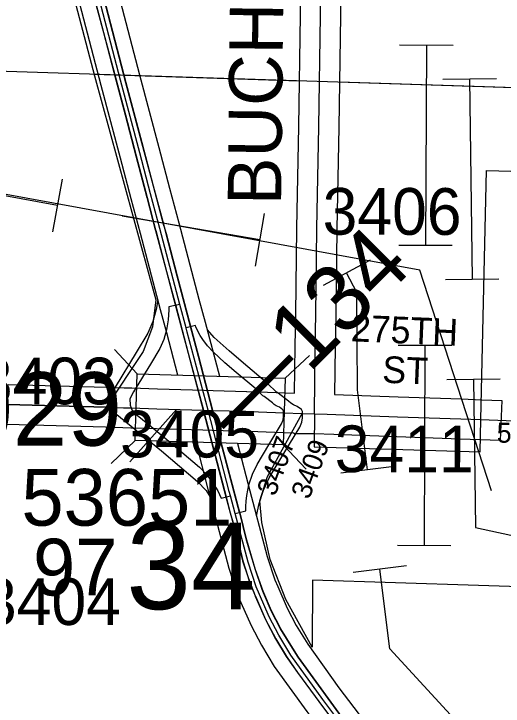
# Model space of a CAD drawing. Extents: x -157.2 to -99.3, y 12.2 to 46.2.
# Drawn here: x -143.818 to -143.085, y 23.189 to 24.227 of the extents above; entities that cross this region are included whole.
import ezdxf

# ---------------------------------------------------------------- set-up
doc = ezdxf.new("R2010")
doc.units = 0
for name, color, linetype in [('tdCoCorpBndry', 7, 'Continuous'), ('tdCoDivCarto', 7, 'Continuous'), ('tdCoInt', 7, 'Continuous'), ('tdCoIntCL', 7, 'Continuous'), ('tdCoIntRamp', 7, 'Continuous'), ('tdCoIntRte', 7, 'Continuous'), ('tdCoPipe', 7, 'Continuous'), ('tdCoPipe1', 7, 'Continuous'), ('tdCoPipe2', 7, 'Continuous'), ('tdCoSecRdNmbr', 7, 'Continuous'), ('tdCoSecRdTxt', 7, 'Continuous'), ('tdCoSecRteBand', 7, 'Continuous'), ('tdCoSecRteCL', 7, 'Continuous'), ('tdCoSectLine', 7, 'Continuous'), ('tdCoSectLinePart', 7, 'Continuous'), ('tdCoSectNmbr', 7, 'Continuous'), ('tdCoStrucNonDivPri', 7, 'Continuous'), ('tdCoStrucPriMaintName', 7, 'Continuous'), ('tdCoStrucSecCoName', 7, 'Continuous'), ('tdCoStrucSecFHWANum', 7, 'Continuous'), ('tdCoSurfConc', 7, 'Continuous'), ('tdCoSurfConcUnbanded', 7, 'Continuous'), ('tdCoSurfEarth', 7, 'Continuous'), ('tdStHwyIntRefPost1', 7, 'Continuous')]:
    doc.layers.add(name, color=color, linetype=linetype)

msp = doc.modelspace()

# ---------------------------------------------------------------- linework, layer by layer
at = {"layer": 'tdCoCorpBndry'}
for points in [[(-143.7635, 24.3875), (-143.6972, 24.1343), (-143.6054, 23.7984), (-143.6103, 23.7579), (-143.6243, 23.7211), (-143.68, 23.6375), (-143.8278, 23.6417), (-143.8666, 23.6435), (-143.8652, 23.7494), (-143.8627, 23.9001), (-143.861, 24.0683), (-143.8604, 24.1421), (-144.3519, 24.154), (-144.3395, 24.6706)], [(-142.873, 23.3623), (-143.3705, 23.3785), (-143.371, 23.2779), (-143.4103, 23.3495), (-143.4338, 23.4091), (-143.4466, 23.4647), (-143.4493, 23.4974), (-143.438, 23.5338), (-143.3862, 23.6283), (-143.3676, 23.6276), (-143.368, 23.5781), (-143.1194, 23.5705), (-143.1181, 23.6189), (-143.11, 23.9926), (-142.8725, 23.9857)]]:
    msp.add_lwpolyline(points, dxfattribs=at)
at = {"layer": 'tdCoDivCarto'}
for points in [[(-143.5922, 23.9073), (-143.5929, 23.9102), (-143.6087, 23.9689), (-143.626, 24.034), (-143.6499, 24.124), (-143.6829, 24.2512), (-143.7118, 24.3607), (-143.7224, 24.4007), (-143.729, 24.4226), (-143.7384, 24.45), (-143.75, 24.4796), (-143.7606, 24.5035), (-143.7754, 24.5309), (-143.7875, 24.5501), (-143.803, 24.5748), (-143.8321, 24.614), (-143.8881, 24.6821), (-143.9875, 24.8034), (-144.0014, 24.8205), (-144.0032, 24.8226)], [(-143.5922, 23.9073), (-143.5929, 23.9102), (-143.6087, 23.9689), (-143.626, 24.034), (-143.6499, 24.124), (-143.6829, 24.2512), (-143.7118, 24.3607), (-143.7224, 24.4007), (-143.729, 24.4226), (-143.7384, 24.45), (-143.75, 24.4796), (-143.7606, 24.5035), (-143.7754, 24.5309), (-143.7875, 24.5501), (-143.803, 24.5748), (-143.8321, 24.614), (-143.8881, 24.6821), (-143.9875, 24.8034), (-144.0014, 24.8205), (-144.0032, 24.8226)], [(-143.9933, 24.7888), (-143.9769, 24.7688), (-143.8797, 24.6499), (-143.8435, 24.6055), (-143.8242, 24.5806), (-143.8077, 24.5577), (-143.7951, 24.538), (-143.7843, 24.5182), (-143.7707, 24.4916), (-143.7596, 24.4677), (-143.752, 24.4472), (-143.7436, 24.4238), (-143.7362, 24.3979), (-143.7152, 24.3192), (-143.7024, 24.2699), (-143.6837, 24.1994), (-143.6649, 24.1281), (-143.6509, 24.0761), (-143.6348, 24.0142), (-143.6186, 23.952), (-143.6058, 23.9037)], [(-143.9933, 24.7888), (-143.9769, 24.7688), (-143.8797, 24.6499), (-143.8435, 24.6055), (-143.8242, 24.5806), (-143.8077, 24.5577), (-143.7951, 24.538), (-143.7843, 24.5182), (-143.7707, 24.4916), (-143.7596, 24.4677), (-143.752, 24.4472), (-143.7436, 24.4238), (-143.7362, 24.3979), (-143.7152, 24.3192), (-143.7024, 24.2699), (-143.6837, 24.1994), (-143.6649, 24.1281), (-143.6509, 24.0761), (-143.6348, 24.0142), (-143.6186, 23.952), (-143.6058, 23.9037)], [(-143.6058, 23.9037), (-143.6055, 23.9027), (-143.5892, 23.8408), (-143.5756, 23.7896)], [(-143.6058, 23.9037), (-143.6055, 23.9027), (-143.5892, 23.8408), (-143.5756, 23.7896)], [(-143.553, 23.7585), (-143.5729, 23.8342), (-143.5895, 23.8973), (-143.5922, 23.9073)], [(-143.553, 23.7585), (-143.5729, 23.8342), (-143.5895, 23.8973), (-143.5922, 23.9073)], [(-143.5756, 23.7896), (-143.5567, 23.7185), (-143.534, 23.6332), (-143.5239, 23.5949), (-143.4999, 23.503)], [(-143.5756, 23.7896), (-143.5567, 23.7185), (-143.534, 23.6332), (-143.5239, 23.5949), (-143.4999, 23.503)], [(-143.4794, 23.4799), (-143.5101, 23.5945), (-143.5201, 23.6328), (-143.5411, 23.7134), (-143.553, 23.7585)], [(-143.4794, 23.4799), (-143.5101, 23.5945), (-143.5201, 23.6328), (-143.5411, 23.7134), (-143.553, 23.7585)], [(-143.4999, 23.503), (-143.4938, 23.4793), (-143.4837, 23.444), (-143.475, 23.4075), (-143.4673, 23.3838), (-143.4649, 23.3767), (-143.4563, 23.355), (-143.4559, 23.3541)], [(-143.4999, 23.503), (-143.4938, 23.4793), (-143.4837, 23.444), (-143.475, 23.4075), (-143.4673, 23.3838), (-143.4649, 23.3767), (-143.4563, 23.355), (-143.4559, 23.3541)], [(-143.4434, 23.3595), (-143.4454, 23.3642), (-143.4465, 23.3672), (-143.4558, 23.3938), (-143.4691, 23.4384), (-143.4792, 23.4791), (-143.4794, 23.4799)], [(-143.4434, 23.3595), (-143.4454, 23.3642), (-143.4465, 23.3672), (-143.4558, 23.3938), (-143.4691, 23.4384), (-143.4792, 23.4791), (-143.4794, 23.4799)], [(-143.4559, 23.3541), (-143.4408, 23.3195), (-143.4255, 23.2904), (-143.4097, 23.264), (-143.3929, 23.2398), (-143.354, 23.1868), (-143.3032, 23.1195), (-143.2484, 23.0455), (-143.2043, 22.9861), (-143.1323, 22.8896), (-143.0588, 22.7913), (-142.9651, 22.6655), (-142.8716, 22.5382), (-142.7826, 22.4199), (-142.7192, 22.3353), (-142.6903, 22.2958), (-142.6501, 22.2411), (-142.6018, 22.1765), (-142.5143, 22.0583)], [(-143.4559, 23.3541), (-143.4408, 23.3195), (-143.4255, 23.2904), (-143.4097, 23.264), (-143.3929, 23.2398), (-143.354, 23.1868), (-143.3032, 23.1195), (-143.2484, 23.0455), (-143.2043, 22.9861), (-143.1323, 22.8896), (-143.0588, 22.7913), (-142.9651, 22.6655), (-142.8716, 22.5382), (-142.7826, 22.4199), (-142.7192, 22.3353), (-142.6903, 22.2958), (-142.6501, 22.2411), (-142.6018, 22.1765), (-142.5143, 22.0583)], [(-142.4471, 21.9916), (-142.4824, 22.0394), (-142.532, 22.106), (-142.5776, 22.1674), (-142.6171, 22.2204), (-142.6871, 22.3149), (-142.7295, 22.3719), (-142.7791, 22.4394), (-142.8255, 22.5016), (-142.8642, 22.5524), (-142.9525, 22.671), (-143.0447, 22.795), (-143.1374, 22.9191), (-143.223, 23.0347), (-143.316, 23.159), (-143.3917, 23.2631), (-143.4003, 23.2762), (-143.4181, 23.3055), (-143.4319, 23.3324), (-143.4434, 23.3595)], [(-142.4471, 21.9916), (-142.4824, 22.0394), (-142.532, 22.106), (-142.5776, 22.1674), (-142.6171, 22.2204), (-142.6871, 22.3149), (-142.7295, 22.3719), (-142.7791, 22.4394), (-142.8255, 22.5016), (-142.8642, 22.5524), (-142.9525, 22.671), (-143.0447, 22.795), (-143.1374, 22.9191), (-143.223, 23.0347), (-143.316, 23.159), (-143.3917, 23.2631), (-143.4003, 23.2762), (-143.4181, 23.3055), (-143.4319, 23.3324), (-143.4434, 23.3595)]]:
    msp.add_lwpolyline(points, dxfattribs=at)
at = {"layer": 'tdCoInt'}
for points in [[(-143.5096, 23.6838), (-143.531, 23.7645), (-143.5403, 23.7991), (-143.5702, 23.9134), (-143.5844, 23.9652), (-143.6004, 24.0264), (-143.6294, 24.1353), (-143.6844, 24.3462), (-143.7073, 24.4317), (-143.7171, 24.4589), (-143.7267, 24.4844), (-143.7387, 24.5102), (-143.7531, 24.5373), (-143.7646, 24.5587), (-143.781, 24.584), (-143.8145, 24.6283), (-143.8321, 24.6489), (-143.8888, 24.7178), (-143.9594, 24.805), (-143.9795, 24.8291), (-144.0027, 24.8578), (-144.0602, 24.9275), (-144.149, 25.0361), (-144.2054, 25.1047)], [(-143.5722, 23.6857), (-143.589, 23.749), (-143.5983, 23.7837), (-143.6282, 23.8978), (-143.6423, 23.9497), (-143.6584, 24.0111), (-143.6874, 24.12), (-143.7424, 24.3308)], [(-143.5454, 23.5849), (-143.5227, 23.497), (-143.5155, 23.4703), (-143.496, 23.3965), (-143.4833, 23.358), (-143.4778, 23.3449), (-143.4625, 23.3104), (-143.4472, 23.281), (-143.4278, 23.2491), (-143.3792, 23.1815), (-143.3341, 23.1217), (-143.2533, 23.0127), (-143.1663, 22.8956), (-143.0759, 22.7746), (-142.9829, 22.6497), (-142.916, 22.5593), (-142.8855, 22.5183), (-142.8068, 22.4137), (-142.7483, 22.3345), (-142.7136, 22.2878), (-142.6082, 22.1457), (-142.5463, 22.0618), (-142.4581, 21.9446), (-142.4099, 21.8795)], [(-143.4829, 23.583), (-143.4647, 23.5124), (-143.4575, 23.4858), (-143.4385, 23.4136), (-143.427, 23.379), (-143.4227, 23.3686), (-143.4084, 23.3365), (-143.3949, 23.3104), (-143.3777, 23.2823), (-143.3309, 23.217), (-143.286, 23.1577), (-143.2051, 23.0485), (-143.1181, 22.9314), (-143.0279, 22.8105), (-142.9347, 22.6855), (-142.8678, 22.5951), (-142.8374, 22.5542), (-142.7587, 22.4496), (-142.7, 22.3702), (-142.6654, 22.3235), (-142.56, 22.1814), (-142.4982, 22.0977), (-142.4101, 21.9806), (-142.3821, 21.9428)]]:
    msp.add_lwpolyline(points, dxfattribs=at)
at = {"layer": 'tdCoIntCL'}
for points in [[(-143.5693, 23.7914), (-143.5992, 23.9056), (-143.6133, 23.9574), (-143.6294, 24.0188), (-143.6584, 24.1276), (-143.7134, 24.3385), (-143.7333, 24.413), (-143.7359, 24.4227), (-143.7453, 24.4485), (-143.7544, 24.4728), (-143.7655, 24.4968), (-143.7795, 24.5231), (-143.7905, 24.5434), (-143.8056, 24.5668), (-143.8349, 24.6055), (-143.8379, 24.6095), (-143.8551, 24.6296), (-143.9121, 24.6988), (-143.9887, 24.7929), (-144.0095, 24.8177), (-144.0259, 24.8388), (-144.0349, 24.8497), (-144.0898, 24.9163)], [(-143.5693, 23.7914), (-143.586, 23.788), (-143.5859, 23.7834), (-143.5867, 23.7684), (-143.5892, 23.7537), (-143.5935, 23.7393), (-143.5994, 23.7256), (-143.6133, 23.7023), (-143.6387, 23.6607), (-143.6443, 23.6501), (-143.6438, 23.6405), (-143.6424, 23.6364), (-143.6414, 23.6336), (-143.6384, 23.6296), (-143.6126, 23.6085), (-143.5829, 23.5843), (-143.5398, 23.5478), (-143.5294, 23.5368), (-143.5203, 23.5248), (-143.5124, 23.512), (-143.5073, 23.5012), (-143.4937, 23.5047)], [(-143.56, 23.7568), (-143.5693, 23.7914)], [(-143.4865, 23.4781), (-143.4705, 23.482), (-143.4705, 23.4887), (-143.4701, 23.4969), (-143.4692, 23.5051), (-143.4659, 23.5213), (-143.4607, 23.537), (-143.4537, 23.5519), (-143.4362, 23.5813), (-143.4172, 23.6126), (-143.4147, 23.6188), (-143.414, 23.6237), (-143.4138, 23.6293), (-143.414, 23.6316), (-143.4152, 23.6338), (-143.4202, 23.6375), (-143.4249, 23.6395), (-143.4278, 23.6415), (-143.4305, 23.6439), (-143.4429, 23.6535), (-143.4448, 23.6545), (-143.4557, 23.6651), (-143.4848, 23.6896), (-143.5018, 23.7041), (-143.5195, 23.7204), (-143.5277, 23.7295), (-143.5348, 23.7391), (-143.5387, 23.7453), (-143.5422, 23.7517), (-143.5454, 23.7583), (-143.5461, 23.7601), (-143.56, 23.7568)], [(-143.4937, 23.5047), (-143.4954, 23.5111), (-143.5271, 23.633), (-143.5582, 23.75), (-143.56, 23.7568)], [(-143.4865, 23.4781), (-143.4937, 23.5047)], [(-142.5223, 22.0797), (-142.5841, 22.1636), (-142.6895, 22.3057), (-142.7242, 22.3524), (-142.7828, 22.4317), (-142.8615, 22.5362), (-142.8919, 22.5772), (-142.9588, 22.6676), (-143.0519, 22.7926), (-143.1422, 22.9135), (-143.2292, 23.0306), (-143.3101, 23.1397), (-143.3551, 23.1992), (-143.4028, 23.2657), (-143.421, 23.2957), (-143.4355, 23.3234), (-143.4502, 23.3567), (-143.4552, 23.3685), (-143.4672, 23.4051), (-143.4865, 23.4781)]]:
    msp.add_lwpolyline(points, dxfattribs=at)
at = {"layer": 'tdCoIntRamp'}
for points in [[(-143.6022, 23.7987), (-143.6047, 23.7838), (-143.6101, 23.7659), (-143.6175, 23.7487), (-143.6349, 23.7196), (-143.6665, 23.6676), (-143.6736, 23.6544), (-143.673, 23.6423), (-143.6712, 23.6372)], [(-143.3855, 23.6283), (-143.3857, 23.6312), (-143.3873, 23.634), (-143.3934, 23.6386), (-143.3993, 23.6411), (-143.403, 23.6436), (-143.4064, 23.6467), (-143.4218, 23.6587), (-143.4243, 23.6599), (-143.4378, 23.6732), (-143.4742, 23.7037), (-143.4955, 23.7219), (-143.5177, 23.7422), (-143.5278, 23.7536), (-143.5283, 23.7543)], [(-143.6712, 23.6372), (-143.6699, 23.6337), (-143.6662, 23.6288), (-143.5969, 23.5721), (-143.5429, 23.5264), (-143.53, 23.5127), (-143.5244, 23.5035)], [(-143.4546, 23.4748), (-143.4506, 23.4934), (-143.4441, 23.513), (-143.4353, 23.5317), (-143.4135, 23.5684), (-143.3897, 23.6075), (-143.3866, 23.6152), (-143.3857, 23.6214), (-143.3855, 23.6283)]]:
    msp.add_lwpolyline(points, dxfattribs=at)
at = {"layer": 'tdCoIntRte'}
for points in [[(-143.7028, 24.2699), (-143.684, 24.1994), (-143.6653, 24.1281), (-143.6512, 24.0761), (-143.6352, 24.0142), (-143.6189, 23.952), (-143.6062, 23.9037), (-143.6059, 23.9027), (-143.5896, 23.8408), (-143.576, 23.7896), (-143.557, 23.7185), (-143.5344, 23.6332), (-143.5242, 23.5949), (-143.5003, 23.503), (-143.4942, 23.4793), (-143.4841, 23.444), (-143.4754, 23.4075), (-143.4676, 23.3838), (-143.4653, 23.3767), (-143.4567, 23.355), (-143.4563, 23.3541), (-143.4411, 23.3195), (-143.4259, 23.2904), (-143.4101, 23.264), (-143.3933, 23.2398), (-143.3543, 23.1868)], [(-143.7028, 24.2699), (-143.684, 24.1994), (-143.6653, 24.1281), (-143.6512, 24.0761), (-143.6352, 24.0142), (-143.6189, 23.952), (-143.6062, 23.9037), (-143.6059, 23.9027), (-143.5896, 23.8408), (-143.576, 23.7896), (-143.557, 23.7185), (-143.5344, 23.6332), (-143.5242, 23.5949), (-143.5003, 23.503), (-143.4942, 23.4793), (-143.4841, 23.444), (-143.4754, 23.4075), (-143.4676, 23.3838), (-143.4653, 23.3767), (-143.4567, 23.355), (-143.4563, 23.3541), (-143.4411, 23.3195), (-143.4259, 23.2904), (-143.4101, 23.264), (-143.3933, 23.2398), (-143.3543, 23.1868)], [(-143.3164, 23.159), (-143.3921, 23.2631), (-143.4007, 23.2762), (-143.4184, 23.3055), (-143.4323, 23.3324), (-143.4438, 23.3595), (-143.4458, 23.3642), (-143.4469, 23.3672), (-143.4562, 23.3938), (-143.4695, 23.4384), (-143.4796, 23.4791), (-143.4798, 23.4799), (-143.5104, 23.5945), (-143.5204, 23.6328), (-143.5415, 23.7134), (-143.5534, 23.7585), (-143.5733, 23.8342), (-143.5899, 23.8973), (-143.5925, 23.9073), (-143.5933, 23.9102), (-143.6091, 23.9689), (-143.6263, 24.034), (-143.6503, 24.124), (-143.6833, 24.2512)], [(-143.3164, 23.159), (-143.3921, 23.2631), (-143.4007, 23.2762), (-143.4184, 23.3055), (-143.4323, 23.3324), (-143.4438, 23.3595), (-143.4458, 23.3642), (-143.4469, 23.3672), (-143.4562, 23.3938), (-143.4695, 23.4384), (-143.4796, 23.4791), (-143.4798, 23.4799), (-143.5104, 23.5945), (-143.5204, 23.6328), (-143.5415, 23.7134), (-143.5534, 23.7585), (-143.5733, 23.8342), (-143.5899, 23.8973), (-143.5925, 23.9073), (-143.5933, 23.9102), (-143.6091, 23.9689), (-143.6263, 24.034), (-143.6503, 24.124), (-143.6833, 24.2512)]]:
    msp.add_lwpolyline(points, dxfattribs=at)
at = {"layer": 'tdCoPipe'}
for p, q in [((-143.7455, 23.9795), (-143.76, 23.9004)), ((-143.4428, 23.9282), (-143.4563, 23.8492)), ((-143.2841, 23.8578), (-143.3548, 23.8202)), ((-143.2484, 23.5488), (-143.3279, 23.5389)), ((-143.2298, 23.3999), (-143.3094, 23.39))]:
    msp.add_line(p, q, dxfattribs=at)
for points in [[(-143.1022, 23.5122), (-143.2095, 23.8428), (-143.9285, 23.9743), (-144.6565, 24.6805), (-145.5794, 24.8267), (-145.6123, 26.3736), (-146.0293, 26.3674), (-146.0413, 27.397)], [(-143.7528, 23.9399), (-143.9223, 23.9709), (-144.0147, 24.0605)], [(-143.4496, 23.8887), (-143.6557, 23.9238)], [(-143.2881, 23.5438), (-143.3031, 23.6638), (-143.3039, 23.8097), (-143.3194, 23.839)], [(-143.1335, 23.143), (-143.1358, 23.1459), (-143.2547, 23.2753), (-143.2696, 23.395)]]:
    msp.add_lwpolyline(points, dxfattribs=at)
at = {"layer": 'tdCoPipe1'}
for p, q in [((-143.1752, 24.1292), (-143.095, 24.1302)), ((-143.1713, 23.8292), (-143.0912, 23.8302)), ((-143.1694, 23.6792), (-143.0892, 23.6802))]:
    msp.add_line(p, q, dxfattribs=at)
for points in [[(-143.1351, 24.1297), (-143.1312, 23.8297)], [(-143.1293, 23.6797), (-143.1265, 23.4575), (-143.0506, 23.4406)]]:
    msp.add_lwpolyline(points, dxfattribs=at)
at = {"layer": 'tdCoPipe2'}
for p, q in [((-143.24, 24.1807), (-143.1598, 24.1804)), ((-143.2414, 23.8807), (-143.1612, 23.8804)), ((-143.242, 23.7307), (-143.1619, 23.7304)), ((-143.2434, 23.4307), (-143.1632, 23.4304))]:
    msp.add_line(p, q, dxfattribs=at)
for points in [[(-143.1999, 24.1806), (-143.2013, 23.8806)], [(-143.202, 23.7306), (-143.2033, 23.4306)]]:
    msp.add_lwpolyline(points, dxfattribs=at)
at = {"layer": 'tdCoSecRteBand'}
for points in [[(-143.3286, 24.3949), (-143.3288, 24.2249), (-143.3288, 24.2247), (-143.3288, 24.2246), (-143.331, 24.0576), (-143.3311, 24.0575), (-143.3311, 24.0574), (-143.3343, 23.9051), (-143.3357, 23.7755), (-143.3357, 23.7754), (-143.3357, 23.7753), (-143.3367, 23.7281), (-143.3374, 23.6565), (-143.242, 23.6531), (-143.1471, 23.6499), (-143.1471, 23.6499), (-143.1471, 23.6499), (-143.117, 23.6488), (-143.087, 23.6478), (-143.0891, 23.5878), (-143.1191, 23.5889), (-143.1491, 23.5899), (-143.2441, 23.5931), (-143.2441, 23.5931), (-143.2441, 23.5931), (-143.3387, 23.5965), (-143.3387, 23.5965), (-143.3683, 23.5976), (-143.3979, 23.5979), (-143.3979, 23.5987), (-143.3987, 23.5987), (-143.4145, 23.5993), (-143.4527, 23.6007), (-143.4713, 23.6014), (-143.5209, 23.6028), (-143.5349, 23.6032), (-143.6046, 23.6053), (-143.6429, 23.6064), (-143.6547, 23.6068), (-143.6808, 23.6075), (-143.8286, 23.6117)], [(-143.8266, 23.6717), (-143.6791, 23.6675), (-143.6791, 23.6675), (-143.6791, 23.6675), (-143.6529, 23.6667), (-143.6411, 23.6664), (-143.6029, 23.6653), (-143.5331, 23.6632), (-143.5192, 23.6628), (-143.4695, 23.6613), (-143.4694, 23.6613), (-143.4692, 23.6613), (-143.4505, 23.6606), (-143.4123, 23.6593), (-143.3974, 23.6587), (-143.3967, 23.7288), (-143.3967, 23.729), (-143.3967, 23.7292), (-143.3957, 23.7764), (-143.3943, 23.9059), (-143.3942, 23.9061), (-143.3942, 23.9062), (-143.391, 24.0585), (-143.3888, 24.2252), (-143.3886, 24.3952)]]:
    msp.add_lwpolyline(points, dxfattribs=at)
at = {"layer": 'tdCoSecRteCL'}
for points in [[(-143.3676, 23.6276), (-143.3667, 23.7285), (-143.3657, 23.7759), (-143.3643, 23.9056), (-143.361, 24.058), (-143.3588, 24.225), (-143.3586, 24.3951), (-143.3561, 24.5727), (-143.3559, 24.7448), (-143.3541, 24.8869), (-143.3541, 24.9325), (-143.3529, 24.9399), (-143.3497, 24.9443), (-143.3443, 24.9488), (-143.3277, 24.9603)], [(-143.8666, 23.6435), (-143.8278, 23.6417), (-143.68, 23.6375), (-143.6538, 23.6367), (-143.642, 23.6364), (-143.6038, 23.6353), (-143.534, 23.6332), (-143.5201, 23.6328), (-143.4703, 23.6314), (-143.4516, 23.6307), (-143.4134, 23.6293), (-143.3862, 23.6283), (-143.3676, 23.6276)], [(-143.3676, 23.6276), (-143.3488, 23.6269), (-143.243, 23.6231), (-143.1481, 23.6199), (-143.1181, 23.6189), (-143.0426, 23.6162), (-142.9982, 23.6152), (-142.9825, 23.6147), (-142.9262, 23.613), (-142.9113, 23.6124), (-142.8699, 23.6107), (-142.8157, 23.6085), (-142.7996, 23.6078), (-142.7845, 23.6071), (-142.7631, 23.6061), (-142.7459, 23.6053), (-142.7015, 23.6034), (-142.6872, 23.6026), (-142.6098, 23.5985), (-142.5877, 23.5973)]]:
    msp.add_lwpolyline(points, dxfattribs=at)
at = {"layer": 'tdCoSectLine'}
msp.add_lwpolyline([(-143.8607, 24.1421), (-142.8668, 24.1102)], dxfattribs=at)
at = {"layer": 'tdCoSectLinePart'}
for points in [[(-143.6983, 24.1369), (-143.3907, 24.127)], [(-143.3307, 24.1251), (-142.9262, 24.1121)]]:
    msp.add_lwpolyline(points, dxfattribs=at)
at = {"layer": 'tdCoStrucNonDivPri'}
for p, q in [((-143.6331, 23.6875), (-143.6674, 23.7239)), ((-143.4115, 23.681), (-143.3751, 23.7153)), ((-143.6361, 23.5875), (-143.6724, 23.5532)), ((-143.4145, 23.581), (-143.3802, 23.5446))]:
    msp.add_line(p, q, dxfattribs=at)
msp.add_lwpolyline([(-143.6331, 23.6875), (-143.4115, 23.681), (-143.4145, 23.581), (-143.6361, 23.5875)], close=True, dxfattribs=at)
at = {"layer": 'tdCoStrucSecFHWANum'}
msp.add_line((-143.6442, 23.5558), (-143.5745, 23.6343), dxfattribs=at)
at = {"layer": 'tdCoSurfConc'}
for p, q in [((-143.68, 23.6375), (-143.6538, 23.6367)), ((-143.4134, 23.6293), (-143.3862, 23.6283)), ((-143.3862, 23.6283), (-143.3676, 23.6276))]:
    msp.add_line(p, q, dxfattribs=at)
for points in [[(-143.8666, 23.6435), (-143.8278, 23.6417), (-143.68, 23.6375)], [(-143.6538, 23.6367), (-143.642, 23.6364), (-143.6038, 23.6353), (-143.534, 23.6332), (-143.5201, 23.6328), (-143.4703, 23.6314), (-143.4516, 23.6307), (-143.4134, 23.6293)], [(-143.3676, 23.6276), (-143.3488, 23.6269), (-143.243, 23.6231), (-143.1481, 23.6199), (-143.1181, 23.6189)]]:
    msp.add_lwpolyline(points, dxfattribs=at)
at = {"layer": 'tdCoSurfConcUnbanded'}
msp.add_lwpolyline([(-143.1181, 23.6189), (-143.0426, 23.6162), (-142.9982, 23.6152), (-142.9825, 23.6147), (-142.9262, 23.613), (-142.9113, 23.6124)], dxfattribs=at)
at = {"layer": 'tdCoSurfEarth'}
msp.add_lwpolyline([(-143.3676, 23.6276), (-143.3667, 23.7285), (-143.3657, 23.7759), (-143.3643, 23.9056), (-143.361, 24.058), (-143.3588, 24.225), (-143.3586, 24.3951), (-143.3561, 24.5727), (-143.3559, 24.7448), (-143.3541, 24.8869), (-143.3541, 24.9325), (-143.3529, 24.9399), (-143.3497, 24.9443), (-143.3443, 24.9488), (-143.3277, 24.9603)], dxfattribs=at)

# ---------------------------------------------------------------- texts
at = {"layer": 'tdCoSecRdNmbr'}
for s, height, rotation, p in [('3406', 0.07, 359.8906, (-143.3555, 23.8963)), ('3403', 0.07, 359.8902, (-143.8721, 23.6422)), ('3405', 0.07, 359.8904, (-143.659, 23.5624)), ('3411', 0.07, 359.8906, (-143.3373, 23.5403)), ('500', 0.03, 359.8945, (-143.0945, 23.5844)), ('3407', 0.03, 69.8905, (-143.4267, 23.5028)), ('3409', 0.03, 69.8905, (-143.3755, 23.4981)), ('3404', 0.07, 359.8902, (-143.866, 23.3114))]:
    msp.add_text(s, height=height, rotation=rotation, dxfattribs=at).set_placement(p)
at = {"layer": 'tdCoSecRdTxt'}
for s, height, rotation, p in [('BUCHANAN AVE', 0.08, 89.3676, (-143.4177, 23.9402)), ('275TH', 0.04, 357.6312, (-143.3136, 23.7364)), ('ST', 0.04, 357.6312, (-143.2666, 23.6744))]:
    msp.add_text(s, height=height, rotation=rotation, dxfattribs=at).set_placement(p)
at = {"layer": 'tdCoSectNmbr'}
msp.add_text('34', height=0.13, rotation=359.8906, dxfattribs=at).set_placement((-143.6496, 23.3349))
at = {"layer": 'tdCoStrucPriMaintName'}
msp.add_text('97341O029', height=0.11, dxfattribs=at).set_placement((-144.425, 23.58))
at = {"layer": 'tdCoStrucSecCoName'}
msp.add_text('97', height=0.085, dxfattribs=at).set_placement((-143.7894, 23.3554))
at = {"layer": 'tdCoStrucSecFHWANum'}
msp.add_text('53651', height=0.085, dxfattribs=at).set_placement((-143.8068, 23.46))
at = {"layer": 'tdStHwyIntRefPost1'}
msp.add_text('‒‒134', height=0.1, rotation=45, dxfattribs=at).set_placement((-143.4811, 23.5822))

doc.saveas('drawing.dxf')
